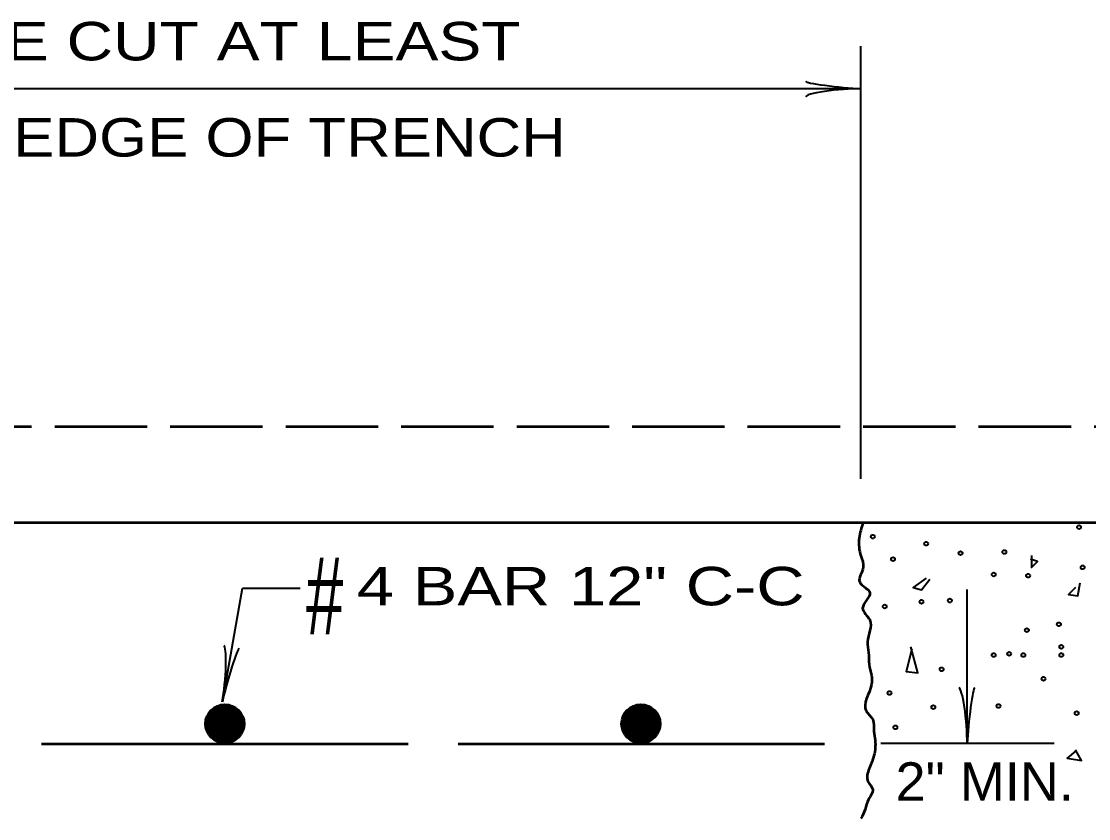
# Model space of a CAD drawing. Extents: x -488 to 193, y 19 to 459.
# Drawn here: x -190.5 to -135, y 318.9 to 360.3 of the extents above; entities that cross this region are included whole.
import ezdxf
from ezdxf.enums import TextEntityAlignment as Align

# ---------------------------------------------------------------- set-up
doc = ezdxf.new("R2010")
doc.units = 0
doc.header["$LTSCALE"] = 0.8
doc.linetypes.add('LONG_DASHED', pattern=[7.5, 6, -1.5])
doc.layers.add('1', color=7, linetype='Continuous', lineweight=40)

msp = doc.modelspace()

# ---------------------------------------------------------------- linework, layer by layer
at = {"layer": '1', "lineweight": 35}
for p, q in [((-146.8628, 336.5494), (-146.8628, 359.0494)), ((-235.8628, 356.8337), (-146.8628, 356.8337)), ((-180.0341, 324.9697), (-178.9922, 330.8786)), ((-178.9922, 330.8786), (-175.9922, 330.8786)), ((-141.3324, 322.8123), (-141.3324, 330.8123)), ((-145.8168, 322.8123), (-136.8168, 322.8123))]:
    msp.add_line(p, q, dxfattribs=at)
at = {"layer": '1', "linetype": 'LONG_DASHED', "lineweight": 53}
msp.add_line((-272.7425, 339.2816), (-112.7425, 339.2816), dxfattribs=at)
at = {"layer": '1', "lineweight": 53}
for p, q in [((-272.7425, 334.2816), (-112.7425, 334.2816)), ((-189.4271, 322.7816), (-170.375, 322.7816)), ((-167.7896, 322.7816), (-148.7425, 322.7816))]:
    msp.add_line(p, q, dxfattribs=at)
at = {"layer": '1', "lineweight": 35}
for points in [[(-137.9872, 332.5697), (-137.9872, 331.9542), (-137.6795, 332.2619), (-138.0488, 332.3851)], [(-143.466, 331.4002), (-144.1432, 330.9077), (-143.7122, 330.7846), (-143.2813, 331.3386)], [(-135.7096, 330.9077), (-136.079, 330.5383), (-135.5865, 330.4767), (-135.4634, 331.1539)], [(-144.2047, 327.7066), (-144.5125, 326.537), (-143.8969, 326.4754), (-144.2662, 327.8297)], [(-135.7096, 322.4126), (-136.1405, 322.0433), (-135.4018, 321.9201), (-135.7096, 322.4742)]]:
    msp.add_lwpolyline(points, dxfattribs=at)
for centre in [(-135.5249, 334.0472), (-146.2362, 333.5547), (-143.466, 333.1853), (-141.6808, 332.6928), (-139.4032, 332.7544), (-145.1897, 332.3851), (-139.9572, 331.5848), (-138.172, 331.5232), (-135.3402, 331.9542), (-145.6206, 329.9228), (-143.7122, 330.169), (-142.2348, 330.2305), (-136.5714, 328.9993), (-138.2335, 328.6916), (-136.4483, 327.8297), (-139.9572, 327.3988), (-139.1569, 327.4604), (-138.4182, 327.3988), (-136.4483, 327.3988), (-142.6658, 326.6601), (-137.3717, 326.1677), (-145.3743, 325.4289), (-143.0967, 324.6902), (-139.7109, 324.7518), (-135.6481, 324.3824), (-145.0665, 323.6438)]:
    msp.add_circle(centre, 0.1, dxfattribs=at)
at = {"layer": '1', "lineweight": 53}
for centre, radius in [((-179.9063, 323.8291), 1), ((-179.9105, 323.8105), 0.9157), ((-179.9125, 323.8682), 0.86), ((-179.9105, 323.8435), 0.8006), ((-179.9002, 323.8167), 0.7367), ((-179.8899, 323.8064), 0.6773), ((-179.8795, 323.8085), 0.6185), ((-158.291, 323.8292), 1), ((-158.2951, 323.8106), 0.9157), ((-158.2972, 323.8683), 0.86), ((-158.2951, 323.8436), 0.8006), ((-158.2848, 323.8168), 0.7367), ((-158.2745, 323.8065), 0.6773), ((-158.2642, 323.8086), 0.6185), ((-179.8734, 323.8167), 0.5611), ((-179.8672, 323.8394), 0.5056), ((-179.8672, 323.8415), 0.4402), ((-179.8569, 323.8455), 0.3756), ((-179.859, 323.8455), 0.316), ((-179.8631, 323.862), 0.2543), ((-179.861, 323.8559), 0.1899), ((-179.8589, 323.862), 0.1383), ((-179.8507, 323.8538), 0.0846), ((-179.8507, 323.8559), 0.0356), ((-158.258, 323.8168), 0.5611), ((-158.2518, 323.8395), 0.5056), ((-158.2519, 323.8415), 0.4402), ((-158.2416, 323.8456), 0.3756), ((-158.2436, 323.8456), 0.316), ((-158.2477, 323.8621), 0.2543), ((-158.2457, 323.856), 0.1899), ((-158.2436, 323.8621), 0.1383), ((-158.2353, 323.8539), 0.0846), ((-158.2354, 323.856), 0.0356)]:
    msp.add_circle(centre, radius, dxfattribs=at)
at = {"layer": '1'}
for centre, major_axis, ratio, start_param, end_param in [((-147.9833, 357.0453), (1.7565, -0.1757), 0.07063, 3.1407148, 5.41811), ((-147.9539, 356.5574), (1.7857, 0.1562), 0.122415, 0.8963533, 3.1415927), ((-180.1167, 326.0923), (-0.1563, -1.7857), 0.122415, 0.8963533, 3.1415927), ((-179.6311, 326.0364), (0.478, 1.6993), 0.07063, 6.2823074, 8.5597026), ((-141.6087, 323.9035), (0.1562, -1.7857), 0.122415, 0.8963533, 3.1415927), ((-141.1208, 323.9328), (0.1757, 1.7565), 0.07063, 6.2823074, 8.5597026)]:
    msp.add_ellipse(centre, major_axis=major_axis, ratio=ratio, start_param=start_param, end_param=end_param, dxfattribs=at)
at = {"layer": '1', "lineweight": 53}
msp.add_spline([(-146.7425, 334.2816), (-146.9522, 333.4717), (-146.8599, 332.5484), (-146.7368, 331.9636), (-146.9215, 331.1942), (-146.3982, 330.6401), (-146.7676, 329.8398), (-146.3982, 329.2242), (-146.5213, 328.0854), (-146.4598, 327.5314), (-146.429, 326.9158), (-146.3059, 326.3618), (-146.3059, 325.8693), (-146.5829, 324.4843), (-146.2443, 324.0534), (-146.1828, 323.4378), (-146.1213, 322.9762), (-146.1828, 322.1758), (-146.429, 321.4987), (-146.4906, 320.8216), (-146.2443, 320.4215), (-146.4598, 319.8982), (-146.6445, 319.375), (-146.8598, 318.8976)], degree=3, dxfattribs=at)

# ---------------------------------------------------------------- texts
at = {"layer": '1'}
for s, height, width, p in [('PAVEMENT TO BE CUT AT LEAST', 2, 1.25, (-191.4725, 358.3016)), ('12" BEYOND EACH EDGE OF TRENCH', 2, 1.2, (-191.4725, 353.3016)), ('#', 4, 0.65, (-174.714, 328.4792)), ('2" MIN.', 2, 1.05, (-140.4264, 319.8254))]:
    msp.add_text(s, height=height, dxfattribs=dict(at, width=width)).set_placement(p, align=Align.CENTER)
at = {"layer": '1', "width": 1.3}
msp.add_text('4 BAR 12" C-C', height=2, dxfattribs=at).set_placement((-173.044, 329.982))

doc.saveas('drawing.dxf')
